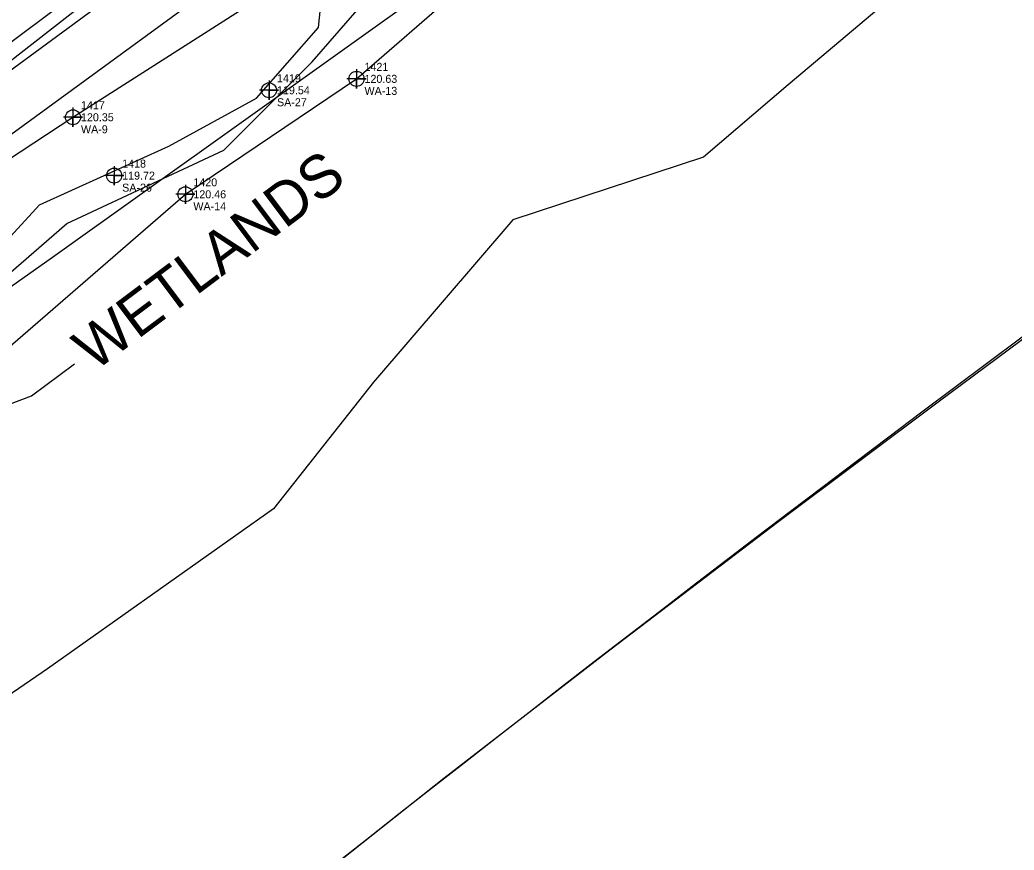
# Model space of a CAD drawing. Extents: x 2186615 to 2188822, y 629899 to 631820.
# Drawn here: x 2187253.2 to 2187346.4, y 630351.9 to 630429.6 of the extents above; entities that cross this region are included whole.
import ezdxf

# ---------------------------------------------------------------- set-up
doc = ezdxf.new("R2010")
doc.units = 0
for name, color, linetype in [('Exist Environmental Wetland Boundary', 7, 'Continuous'), ('Exist Environmental Wetland Boundary Cogo Comment', 7, 'Continuous'), ('Exist Environmental Wetland Boundary Cogo Elevation', 7, 'Continuous'), ('Exist Environmental Wetland Boundary Cogo Number', 7, 'Continuous'), ('Exist Environmental Wetland Boundary Cogo Point CELL', 7, 'Continuous'), ('Exist Environmental Wetland Boundary Leader', 7, 'Continuous'), ('Exist Environmental Wetland Boundary Text', 7, 'Continuous'), ('Exist Hydro Jurisdictional Stream or Body of Water', 7, 'Continuous'), ('Exist Railroads Standard Gauge', 7, 'Continuous'), ('Exist Right of Way Line', 7, 'Continuous'), ('Exist Vegetation Woods Line', 7, 'Continuous'), ('Scratch_Level_1', 7, 'Continuous')]:
    doc.layers.add(name, color=color, linetype=linetype)

msp = doc.modelspace()

# ---------------------------------------------------------------- linework, layer by layer
at = {"layer": 'Exist Environmental Wetland Boundary'}
for points in [[(2187200.333, 630357.676), (2187218.012, 630369.88), (2187243.865, 630391.755), (2187268.738, 630413.3), (2187284.769, 630424.116), (2187304.062, 630440.889), (2187311.728, 630449.237), (2187310.985, 630450.407)], [(2187091.311, 630271.672), (2187085.676, 630287.812), (2187098.271, 630306.167), (2187117.246, 630318.391), (2187145.167, 630331.818), (2187167.383, 630352.861), (2187202.427, 630381.298), (2187228.671, 630401.09), (2187258.21, 630420.516), (2187282.166, 630435.853)]]:
    msp.add_lwpolyline(points, dxfattribs=at)
at = {"layer": 'Exist Environmental Wetland Boundary Cogo Point CELL'}
for points in [[(2187284.769, 630425.016), (2187284.769, 630423.216), (2187284.769, 630424.116), (2187285.669, 630424.116), (2187283.869, 630424.116)], [(2187276.573, 630423.947), (2187276.573, 630422.147), (2187276.573, 630423.047), (2187277.473, 630423.047), (2187275.673, 630423.047)], [(2187258.21, 630421.416), (2187258.21, 630419.616), (2187258.21, 630420.516), (2187259.11, 630420.516), (2187257.31, 630420.516)], [(2187262.067, 630415.948), (2187262.067, 630414.148), (2187262.067, 630415.048), (2187262.967, 630415.048), (2187261.167, 630415.048)], [(2187268.738, 630414.2), (2187268.738, 630412.4), (2187268.738, 630413.3), (2187269.638, 630413.3), (2187267.838, 630413.3)]]:
    msp.add_lwpolyline(points, dxfattribs=at)
for centre in [(2187284.769, 630424.116), (2187276.573, 630423.047), (2187258.21, 630420.516), (2187262.067, 630415.048), (2187268.738, 630413.3)]:
    msp.add_circle(centre, 0.703, dxfattribs=at)
at = {"layer": 'Exist Environmental Wetland Boundary Leader'}
msp.add_lwpolyline([(2187235.079, 630387.141), (2187254.322, 630394.422), (2187258.337, 630397.432)], dxfattribs=at)
at = {"layer": 'Exist Hydro Jurisdictional Stream or Body of Water'}
for points in [[(2187197.322, 630361.43), (2187213.945, 630373.562), (2187222.659, 630386.877), (2187241.705, 630395.38), (2187246.836, 630403.358), (2187255.086, 630412.327), (2187267.186, 630417.823), (2187275.409, 630422.294), (2187281.209, 630428.913), (2187281.92, 630435.898), (2187289.055, 630441.644), (2187305.984, 630451.32), (2187327.255, 630464.456), (2187344.34, 630479.914), (2187359.178, 630488.147), (2187368.792, 630495.674), (2187384.724, 630510.856), (2187399.768, 630521.857), (2187428.248, 630541.272), (2187449.565, 630557.041)], [(2187200.333, 630357.676), (2187217.66, 630373.541), (2187219.417, 630375.085), (2187222.068, 630380.972), (2187226.921, 630384.519), (2187239.946, 630392.223), (2187243.455, 630393.717), (2187246.058, 630398.658), (2187250.235, 630404.156), (2187257.633, 630410.563), (2187272.327, 630417.422), (2187280.629, 630425.711), (2187291.154, 630437.828), (2187309.311, 630449.202), (2187326.618, 630461.663), (2187344.871, 630475.57), (2187361.058, 630486.179), (2187383.779, 630505.824), (2187403.688, 630519.913), (2187435.685, 630540.516), (2187447.835, 630554.369)]]:
    msp.add_lwpolyline(points, dxfattribs=at)
at = {"layer": 'Exist Railroads Standard Gauge'}
msp.add_lwpolyline([(2187472.105, 630489.073), (2187449.982, 630473.712), (2187430.999, 630460.445), (2187414.319, 630448.649), (2187398.612, 630437.433), (2187383.688, 630426.68), (2187369.359, 630416.193), (2187352.385, 630403.568), (2187339.381, 630393.934), (2187324.342, 630382.646), (2187308.502, 630370.589), (2187292.949, 630358.567), (2187273.005, 630342.736), (2187257.004, 630329.906), (2187243.764, 630319.095), (2187230.676, 630308.301), (2187217.925, 630297.525), (2187202.302, 630284.355), (2187187.152, 630271.368)], dxfattribs=at)
at = {"layer": 'Exist Right of Way Line'}
msp.add_line((2187154.402, 630354.104), (2188538.851, 631392.039), dxfattribs=at)
for radius in [2893.554, 2763.554]:
    msp.add_arc((2189028.8, 628141.736), radius, 125.65722, 135.708207, dxfattribs=at)
at = {"layer": 'Exist Vegetation Woods Line'}
for points in [[(2187105.726, 630299.086), (2187150.799, 630331.829), (2187206.105, 630372.034), (2187256.074, 630407.258), (2187300.913, 630439.289), (2187349.475, 630473.877), (2187396.874, 630507.865), (2187440.691, 630538.214), (2187466.075, 630555.071), (2187474.722, 630557.755), (2187481.166, 630558.923), (2187486.051, 630559.676), (2187489.303, 630561.136), (2187491.384, 630563.953), (2187492.451, 630570.166), (2187494.251, 630572.315)], [(2187473.569, 630527.3), (2187453.75, 630512.916), (2187435.186, 630501.319), (2187410.074, 630490.236), (2187391.303, 630473.708), (2187377.298, 630457.794), (2187368.165, 630449.57), (2187357.71, 630447.66), (2187342.586, 630438.232), (2187325.212, 630423.547), (2187317.288, 630416.779), (2187299.412, 630410.909), (2187286.374, 630395.698), (2187276.981, 630383.819), (2187255.826, 630368.846), (2187238.494, 630356.985), (2187221.565, 630339.526), (2187197.373, 630321.295), (2187174.715, 630306.11), (2187151.591, 630284.746), (2187135.361, 630271.561)], [(2187230.496, 630408.889), (2187277.266, 630443.245), (2187318.865, 630473.262), (2187330.634, 630477.313), (2187307.147, 630458.864), (2187234.208, 630405.639), (2187193.004, 630375.627), (2187170.079, 630359.227), (2187132.552, 630332.436), (2187105.521, 630312.125)]]:
    msp.add_lwpolyline(points, dxfattribs=at)
at = {"layer": 'Scratch_Level_1'}
msp.add_arc((2189028.8, 628141.736), 2815.554, 125.65722, 135.708207, dxfattribs=at)

# ---------------------------------------------------------------- texts
at = {"layer": 'Exist Environmental Wetland Boundary Cogo Comment'}
for s, p in [('WA-13', (2187285.519, 630422.616)), ('SA-27', (2187277.323, 630421.547)), ('WA-9', (2187258.96, 630419.016)), ('SA-26', (2187262.817, 630413.548)), ('WA-14', (2187269.488, 630411.8))]:
    msp.add_text(s, height=0.75, dxfattribs=at).set_placement(p)
at = {"layer": 'Exist Environmental Wetland Boundary Cogo Elevation'}
for s, p in [('120.63', (2187285.519, 630423.741)), ('119.54', (2187277.323, 630422.672)), ('120.35', (2187258.96, 630420.141)), ('119.72', (2187262.817, 630414.673)), ('120.46', (2187269.488, 630412.925))]:
    msp.add_text(s, height=0.75, dxfattribs=at).set_placement(p)
at = {"layer": 'Exist Environmental Wetland Boundary Cogo Number'}
for s, p in [('1421', (2187285.519, 630424.866)), ('1419', (2187277.323, 630423.797)), ('1417', (2187258.96, 630421.266)), ('1418', (2187262.817, 630415.798)), ('1420', (2187269.488, 630414.05))]:
    msp.add_text(s, height=0.75, dxfattribs=at).set_placement(p)
at = {"layer": 'Exist Environmental Wetland Boundary Text'}
msp.add_text('WETLANDS', height=4, rotation=36.85926, dxfattribs=at).set_placement((2187260.218, 630396.633))

doc.saveas('drawing.dxf')
